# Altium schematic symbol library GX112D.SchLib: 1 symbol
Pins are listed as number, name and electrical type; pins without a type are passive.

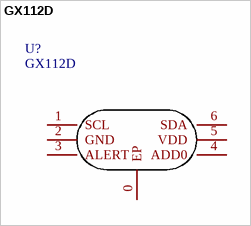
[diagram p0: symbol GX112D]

## GX112D
designator U?
footprint DFN-6-EP_L1.6-W1.6-P0.50-BL
pins: 0 EP, 1 SCL, 2 GND, 3 ALERT, 4 ADD0, 5 VDD, 6 SDA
